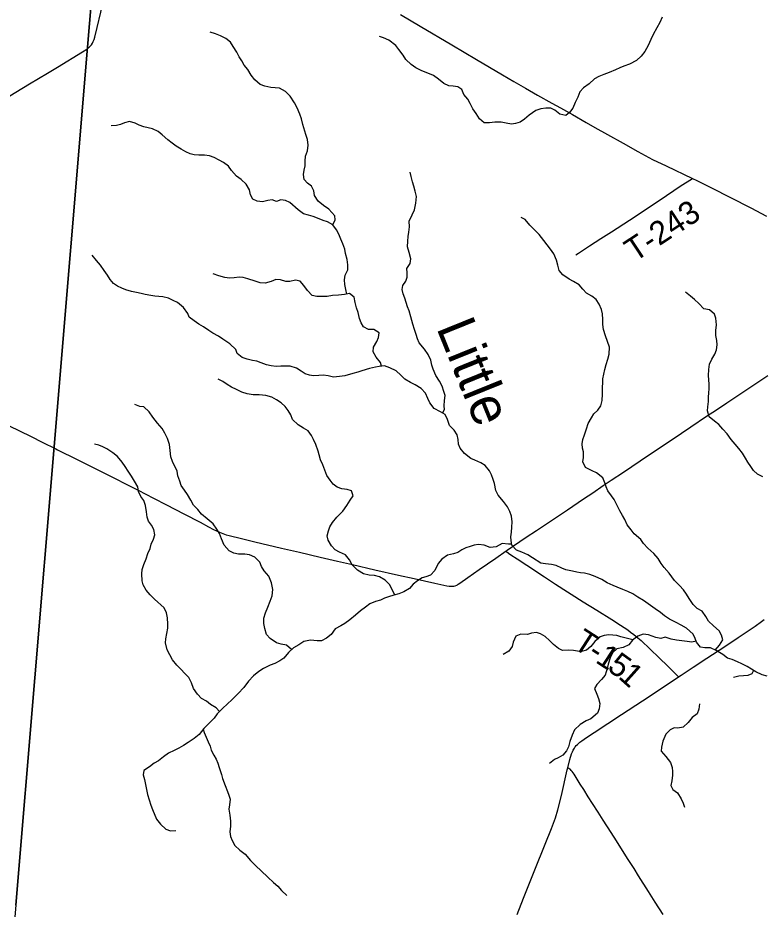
# Model space of a CAD drawing. Extents: x 0 to 1101, y 0 to 440.
# Drawn here: x 442.1 to 496.6, y 333.9 to 399.2 of the extents above; entities that cross this region are included whole.
import ezdxf

# ---------------------------------------------------------------- set-up
doc = ezdxf.new("R2010")
doc.units = 0
for name, color, linetype in [('GM_X_County_Road', 7, 'Continuous'), ('GM_X_Minor_River', 7, 'Continuous'), ('GM_X_Minor_River_Text', 7, 'Continuous'), ('GM_X_State_Route', 7, 'Continuous'), ('GM_X_Township_Road', 7, 'Continuous'), ('GM_X_Township_Road_Text', 7, 'Continuous')]:
    doc.layers.add(name, color=color, linetype=linetype)

msp = doc.modelspace()

# ---------------------------------------------------------------- linework, layer by layer
at = {"layer": 'GM_X_County_Road'}
for points in [[(441.919, 334.219), (444.709, 367.542), (447.185, 397.096), (448.107, 408.104), (416.196, 410.741)], [(447.303, 397.095), (447.325, 397.113), (447.405, 397.19), (447.471, 397.272), (447.537, 397.388), (447.597, 397.508), (447.659, 397.659), (447.718, 397.839), (447.897, 398.547), (448.161, 399.672), (448.67, 401.868), (448.936, 403.031), (449.312, 404.624), (449.637, 405.944), (449.838, 406.778), (450.23, 408.461)], [(470.094, 399.487), (471.558, 398.634), (473.867, 397.266), (475.677, 396.188), (477.57, 395.069), (478.42, 394.569), (479.257, 394.081), (480.151, 393.58), (481.19, 393.003), (481.824, 392.652), (482.698, 392.153), (483.716, 391.57), (484.351, 391.215), (485.281, 390.702), (486.412, 390.054), (487.483, 389.447), (488.569, 388.868), (489.561, 388.391), (491.499, 387.483), (491.811, 387.337), (492.842, 386.815), (495.762, 385.317), (496.923, 384.723)], [(420.004, 380.3), (420.984, 380.916), (423.156, 382.233), (423.231, 382.279), (425.059, 383.399), (428.052, 385.22), (429.936, 386.391), (432.42, 387.903), (433.884, 388.795), (436.362, 390.315), (437.628, 391.104), (438.966, 391.952), (440.938, 393.191), (441.919, 393.801), (442.941, 394.415), (444.239, 395.183), (444.988, 395.638), (446.8, 396.745), (447.132, 396.959), (447.235, 397.039), (447.303, 397.095)]]:
    msp.add_lwpolyline(points, dxfattribs=at)
msp.add_lwpolyline([(539, 244.322), (539, 402.783), (536.69, 402.914), (536.426, 402.929), (536.173, 402.942), (535.046, 402.998), (535.011, 403), (510.324, 404.394), (509.979, 404.414), (498.864, 405.041), (457.454, 407.541), (450.104, 407.972), (448.107, 408.104), (447.185, 397.096), (444.709, 367.542), (441.919, 334.219), (439.492, 305.784), (437.233, 279.3), (437.137, 278.176), (435.213, 255.629), (445.064, 254.562), (483.107, 250.705), (508.328, 247.799), (515.616, 246.993)], close=True, dxfattribs=at)
at = {"layer": 'GM_X_Minor_River'}
for points in [[(489.285, 399.3), (489.097, 398.915), (488.874, 398.52), (488.616, 398.034), (488.451, 397.661), (488.239, 397.231), (488.004, 396.768), (487.737, 396.43), (487.39, 396.117), (486.873, 395.863), (486.472, 395.698), (486.173, 395.578), (485.852, 395.446), (485.382, 395.237), (484.992, 395.095), (484.625, 394.941), (484.326, 394.786), (483.932, 394.405), (483.518, 394.127), (483.24, 393.824), (483.086, 393.439), (482.909, 393.054), (482.72, 392.636), (482.498, 392.309), (482.21, 392.086), (481.778, 392.195), (481.406, 392.474), (481.112, 392.615), (480.747, 392.632), (480.393, 392.581), (480.027, 392.461), (479.531, 392.105), (479.196, 391.814), (478.873, 391.602), (478.518, 391.494), (478.233, 391.464), (477.835, 391.527), (477.482, 391.59), (477.015, 391.608), (476.627, 391.546), (476.239, 391.564), (475.89, 391.842), (475.657, 392.233), (475.399, 392.567), (475.212, 392.98), (475.034, 393.279), (474.754, 393.637), (474.6, 394.004), (474.307, 394.19), (473.954, 394.241), (473.646, 394.258), (473.284, 394.423), (472.901, 394.748), (472.518, 395.016), (472.098, 395.182), (471.679, 395.37), (471.238, 395.594), (470.899, 395.815), (470.495, 396.197), (470.306, 396.519), (469.993, 396.934), (469.758, 397.223), (469.251, 397.618), (468.854, 397.772), (468.559, 397.879)], [(465.157, 384.084), (465.31, 384.434), (465.292, 384.742), (464.866, 385.215), (464.472, 385.484), (464.077, 385.809), (463.799, 386.223), (463.759, 386.577), (463.593, 386.909), (463.288, 387.119), (463.042, 387.408), (462.99, 387.761), (463.04, 388.08), (463.114, 388.409), (463.119, 388.739), (463.147, 389.103), (463.29, 389.499), (463.353, 389.908), (463.291, 390.319), (463.171, 390.697), (462.955, 391.44), (462.847, 391.852), (462.738, 392.184), (462.528, 392.643), (462.34, 393.01), (462.029, 393.516), (461.68, 393.852), (461.239, 394.098), (460.932, 394.126), (460.613, 394.142), (460.158, 394.24), (459.818, 394.371), (459.435, 394.696), (459.167, 395.053), (458.923, 395.467), (458.665, 395.767), (458.487, 396.089), (458.286, 396.377), (458.121, 396.721), (457.853, 397.146), (457.641, 397.457), (457.315, 397.736), (456.93, 397.935), (456.556, 398.067), (456.159, 398.187)], [(466.172, 379.006), (466.11, 379.343), (466.025, 379.709), (465.995, 380.04), (466.046, 380.392), (466.246, 380.787), (466.252, 381.14), (466.189, 381.528), (466.082, 381.974), (466.019, 382.282), (465.877, 382.683), (465.745, 383.038), (465.591, 383.394), (465.425, 383.704), (465.157, 384.084), (464.761, 384.295), (464.432, 384.402), (464.036, 384.568), (463.718, 384.687), (463.355, 384.784), (462.992, 384.892), (462.608, 385.171), (462.001, 385.704), (461.684, 385.869), (461.342, 385.897), (461.033, 385.799), (460.715, 385.907), (460.396, 385.866), (459.995, 385.77), (459.597, 385.81), (459.279, 385.952), (459.125, 386.273), (459.051, 386.65), (458.795, 387.064), (458.435, 387.4), (458.085, 387.633), (457.715, 388.049), (457.504, 388.382), (457.132, 388.65), (456.815, 388.826), (456.453, 389.002), (456.124, 389.122), (455.749, 389.184), (455.338, 389.191), (454.997, 389.219), (454.69, 389.292), (454.373, 389.422), (454.045, 389.621), (453.672, 389.843), (453.379, 390.064), (453.064, 390.308), (452.659, 390.668), (452.355, 390.911), (451.947, 391.111), (451.618, 391.196), (451.311, 391.269), (450.971, 391.389), (450.676, 391.53), (450.256, 391.639), (449.89, 391.554), (449.592, 391.433), (449.306, 391.358), (448.918, 391.341)], [(473.192, 370.279), (473.328, 370.532), (473.309, 370.817), (473.338, 371.192), (473.389, 371.567), (473.28, 371.865), (473.149, 372.254), (472.961, 372.632), (472.694, 373.024), (472.496, 373.494), (472.398, 373.791), (472.324, 374.157), (472.136, 374.581), (471.869, 374.961), (471.465, 375.434), (471.344, 375.72), (471.247, 376.041), (471.139, 376.418), (471.019, 376.807), (470.868, 377.333), (470.738, 377.779), (470.617, 378.077), (470.519, 378.386), (470.433, 378.695), (470.301, 379.027), (470.237, 379.336), (470.288, 379.642), (470.486, 379.947), (470.593, 380.241), (470.587, 380.549), (470.569, 380.868), (470.803, 381.24), (470.865, 381.58), (470.735, 382.049), (470.616, 382.461), (470.634, 382.882), (470.662, 383.223), (470.724, 383.53), (470.775, 383.928), (470.748, 384.349), (470.971, 384.801), (471.125, 385.186), (471.235, 385.663), (471.266, 386.152), (471.18, 386.552), (471.072, 386.907), (470.986, 387.238), (470.877, 387.616), (470.826, 387.947)], [(493.149, 352.906), (493.467, 353.266), (493.713, 353.661), (493.616, 354.004), (493.45, 354.325), (493.045, 354.684), (492.674, 355.02), (492.474, 355.365), (492.195, 355.756), (491.833, 355.955), (491.553, 356.256), (491.263, 356.681), (491.063, 357.015), (490.829, 357.337), (490.537, 357.649), (490.189, 358.007), (489.776, 358.549), (489.418, 358.976), (489.194, 359.264), (488.972, 359.62), (488.67, 360.001), (488.22, 360.372), (487.917, 360.718), (487.716, 361.006), (487.233, 361.435), (486.998, 361.734), (486.719, 362.092), (486.542, 362.481), (486.365, 362.78), (486.176, 363.125), (485.988, 363.515), (485.755, 363.94), (485.566, 364.227), (485.298, 364.584), (485.177, 364.871), (485.068, 365.18), (484.925, 365.524), (484.452, 365.907), (484.135, 366.037), (483.66, 366.295), (483.461, 366.708), (483.512, 367.037), (483.507, 367.436), (483.443, 367.721), (483.402, 368.018), (483.464, 368.336), (483.595, 368.698), (483.738, 369.117), (483.847, 369.525), (484.093, 369.931), (484.268, 370.225), (484.569, 370.504), (484.779, 370.82), (484.888, 371.205), (484.895, 371.661), (484.891, 372.173), (484.919, 372.503), (484.935, 372.787), (485.009, 373.139), (485.083, 373.468), (485.168, 373.843), (485.299, 374.228), (485.396, 374.602), (485.416, 375.103), (485.274, 375.537), (485.121, 375.95), (484.98, 376.396), (484.928, 376.773), (484.934, 377.148), (484.895, 377.559), (484.831, 377.867), (484.666, 378.268), (484.444, 378.602), (484.128, 378.846), (483.721, 379.057), (483.463, 379.369), (483.206, 379.669), (482.788, 379.914), (482.46, 380.09), (482.009, 380.416), (481.74, 380.728), (481.621, 381.128), (481.535, 381.482), (481.337, 381.952), (481.103, 382.298), (480.857, 382.609), (480.611, 382.932), (480.253, 383.37), (479.883, 383.763), (479.591, 384.052), (479.243, 384.456), (478.938, 384.609)], [(457.08, 375.693), (456.765, 375.926), (456.369, 376.148), (456.076, 376.324), (455.669, 376.603), (455.342, 376.802), (454.992, 377.047), (454.631, 377.303), (454.533, 377.589), (454.221, 378.026), (453.781, 378.375), (453.453, 378.539), (453.114, 378.693), (452.693, 378.802), (452.113, 378.856), (451.817, 378.907), (451.408, 378.981), (451.101, 379.054), (450.76, 379.117), (450.407, 379.191), (449.976, 379.323), (449.682, 379.441), (449.365, 379.583), (449.071, 379.769), (448.848, 380.069), (448.647, 380.379), (448.39, 380.725), (448.134, 381.116), (447.843, 381.474), (447.53, 381.854)], [(468.724, 373.714), (468.65, 373.986), (468.314, 374.367), (468.115, 374.78), (468.12, 375.11), (468.377, 375.516), (468.484, 375.811), (468.535, 376.174), (468.151, 376.408), (467.764, 376.403), (467.39, 376.591), (467.224, 376.889), (467.103, 377.21), (466.996, 377.644), (466.876, 377.999), (466.791, 378.388), (466.705, 378.765), (466.379, 379.054), (466.013, 378.969), (465.568, 378.919), (465.134, 378.892), (464.734, 378.818), (464.357, 378.813), (463.97, 378.83), (463.641, 378.904), (463.293, 379.262), (463.025, 379.619), (462.756, 379.942), (462.404, 380.016), (462.003, 379.931), (461.695, 379.925), (461.321, 380.044), (460.979, 380.061), (460.624, 379.93), (460.188, 379.812), (459.824, 379.817), (459.472, 379.937), (458.916, 380.128), (458.576, 380.213), (458.28, 380.24), (457.925, 380.189), (457.571, 380.16), (457.23, 380.222), (456.799, 380.343), (456.39, 380.475)], [(496.647, 365.615), (496.262, 365.814), (495.959, 366.069), (495.769, 366.368), (495.558, 366.679), (495.369, 366.989), (495.169, 367.334), (494.9, 367.68), (494.621, 368.014), (494.318, 368.349), (494.039, 368.752), (493.725, 369.098), (493.434, 369.433), (493.096, 369.689), (492.713, 370.002), (492.595, 370.448), (492.622, 370.744), (492.662, 371.141), (492.679, 371.449), (492.695, 371.767), (492.711, 372.063), (492.705, 372.405), (492.687, 372.724), (492.669, 373.043), (492.687, 373.487), (492.739, 373.862), (492.915, 374.223), (493.138, 374.607), (493.257, 374.924), (493.296, 375.276), (493.267, 375.595), (493.205, 375.972), (493.199, 376.337), (493.251, 376.746), (493.201, 377.225), (493.114, 377.522), (492.732, 377.858), (492.334, 377.921), (491.964, 378.303), (491.649, 378.604), (491.345, 378.848), (490.973, 379.15)], [(488.755, 355.935), (488.416, 356.179), (487.909, 356.54), (487.503, 356.797), (487.119, 357.042), (486.756, 357.207), (486.394, 357.361), (485.975, 357.527), (485.68, 357.645), (485.25, 357.834), (484.843, 358.079), (484.356, 358.303), (483.971, 358.457), (483.585, 358.543), (483.3, 358.582), (483.016, 358.632), (482.698, 358.693), (482.209, 358.792), (481.915, 358.922), (481.507, 359.099), (481.178, 359.173), (480.722, 359.225), (480.381, 359.287), (479.771, 359.661), (479.444, 359.894), (478.991, 360.083), (478.606, 360.226), (478.27, 360.607), (478.206, 360.938), (478.2, 361.223), (478.239, 361.564), (478.267, 361.916), (478.296, 362.314), (478.246, 362.725), (478.114, 363.068), (477.949, 363.412), (477.658, 363.804), (477.255, 364.266), (477.101, 364.61), (476.983, 365.124), (476.885, 365.41), (476.765, 365.765), (476.633, 366.051), (476.308, 366.432), (475.992, 366.631), (475.551, 366.831), (475.256, 366.95), (474.794, 367.321), (474.47, 367.713), (474.349, 368.011), (474.32, 368.342), (474.268, 368.696), (474.034, 369.029), (473.697, 369.376), (473.556, 369.8), (473.39, 370.167), (473.04, 370.366), (472.577, 370.623), (472.252, 371.027), (472.109, 371.359), (471.944, 371.749), (471.619, 372.084), (471.178, 372.353), (470.839, 372.518), (470.432, 372.763), (470.129, 373.064), (469.781, 373.388), (469.328, 373.589), (468.942, 373.743), (468.554, 373.692), (468.268, 373.639), (467.845, 373.544), (467.284, 373.382), (466.974, 373.284), (466.619, 373.176), (466.035, 373.014), (465.635, 372.952), (465.201, 372.925), (464.803, 372.999), (464.451, 373.062), (464.131, 373.032), (463.732, 373.004), (463.436, 373.066), (463.13, 373.162), (462.836, 373.349), (462.498, 373.57), (462.021, 373.714), (461.645, 373.709), (461.337, 373.714), (461.006, 373.707), (460.63, 373.736), (460.29, 373.821), (459.904, 373.952), (459.575, 374.083), (459.268, 374.145), (458.882, 374.23), (458.519, 374.35), (458.136, 374.64), (458.038, 374.938), (457.611, 375.366), (457.08, 375.693)], [(469.691, 356.951), (469.308, 357.719), (468.994, 358.043), (468.565, 358.277), (468.19, 358.374), (467.814, 358.414), (467.394, 358.512), (466.965, 358.757), (466.572, 359.151), (466.372, 359.518), (466.07, 359.899), (465.64, 360.099), (465.323, 360.252), (465.043, 360.563), (464.798, 360.966), (464.746, 361.274), (464.832, 361.648), (464.939, 361.943), (465.127, 362.27), (465.452, 362.652), (465.881, 363.089), (466.172, 363.506), (466.429, 363.911), (466.639, 364.216), (466.508, 364.593), (466.202, 364.678), (465.815, 364.729), (465.464, 364.86), (465.17, 365.07), (464.947, 365.358), (464.713, 365.703), (464.571, 366.104), (464.417, 366.482), (464.24, 366.86), (464.155, 367.214), (464.068, 367.5), (463.904, 367.97), (463.739, 368.337), (463.584, 368.635), (463.35, 368.98), (463.011, 369.179), (462.604, 369.413), (462.2, 369.807), (462.08, 370.15), (461.868, 370.472), (461.667, 370.76), (461.364, 371.026), (461.025, 371.259), (460.674, 371.436), (460.232, 371.568), (459.742, 371.61), (459.309, 371.616), (458.865, 371.68), (458.491, 371.811), (458.084, 372), (457.722, 372.188), (457.406, 372.386), (457.101, 372.585), (456.761, 372.761)], [(462.13, 352.959), (461.759, 353.261), (461.373, 353.347), (461.032, 353.443), (460.547, 353.758), (460.289, 354.047), (460.171, 354.504), (460.085, 354.87), (460.103, 355.256), (460.212, 355.653), (460.378, 356.06), (460.567, 356.49), (460.71, 356.898), (460.751, 357.364), (460.668, 357.843), (460.459, 358.324), (460.111, 358.717), (459.934, 359.038), (459.79, 359.348), (459.443, 359.718), (459.047, 359.895), (458.705, 359.934), (458.227, 359.953), (457.897, 360.027), (457.557, 360.18), (457.199, 360.607), (456.99, 361.077), (456.836, 361.444), (456.647, 361.765), (456.38, 362.168), (455.952, 362.539), (455.536, 362.875), (455.256, 363.21), (454.942, 363.522), (454.742, 363.89), (454.509, 364.315), (454.286, 364.625), (454.029, 364.971), (453.932, 365.291), (453.801, 365.68), (453.738, 366.034), (453.407, 366.723), (453.275, 367.078), (453.225, 367.545), (453.175, 367.99), (453.045, 368.424), (452.846, 368.815), (452.646, 369.148), (452.31, 369.552), (451.952, 369.979), (451.685, 370.37), (451.303, 370.729), (451.018, 370.767), (450.655, 370.898)], [(456.859, 348.411), (456.602, 348.686), (456.184, 348.921), (455.891, 349.164), (455.518, 349.364), (455.238, 349.675), (454.948, 350.09), (454.784, 350.513), (454.607, 350.892), (453.721, 351.805), (453.396, 352.209), (453.197, 352.565), (453.02, 352.92), (452.891, 353.446), (452.907, 353.742), (453.056, 354.513), (453.072, 354.82), (453.045, 355.276), (452.971, 355.642), (452.783, 355.997), (452.086, 356.646), (451.772, 356.958), (451.481, 357.293), (451.259, 357.683), (451.172, 357.992), (451.146, 358.505), (451.185, 358.811), (451.294, 359.185), (451.471, 359.592), (451.591, 360), (451.757, 360.362), (451.853, 360.668), (452.018, 361.052), (452.103, 361.347), (452.029, 361.758), (451.863, 362.057), (451.651, 362.367), (451.542, 362.654), (451.491, 363.041), (451.429, 363.509), (451.298, 363.864), (451.075, 364.175), (450.921, 364.53), (450.858, 364.873), (450.625, 365.298), (450.391, 365.654), (450.146, 366.034), (449.935, 366.356), (449.712, 366.689), (449.376, 367.093), (449.038, 367.372), (448.587, 367.652), (448.293, 367.816), (447.998, 367.934), (447.691, 367.996)], [(478.255, 360.683), (478.02, 360.679), (477.553, 360.732), (477.105, 360.488), (476.682, 360.438), (476.229, 360.605), (475.83, 360.645), (475.499, 360.593), (475.201, 360.507), (474.892, 360.398), (474.604, 360.266), (474.294, 360.066), (473.984, 359.957), (473.561, 359.861), (473.123, 359.583), (472.867, 359.257), (472.62, 358.749), (472.295, 358.401), (471.974, 358.281), (471.688, 358.205), (471.354, 357.994), (471.042, 357.749), (470.763, 357.434), (470.361, 357.19), (469.982, 357.037), (469.615, 356.929), (469.226, 356.81), (468.939, 356.712), (468.629, 356.58), (468.286, 356.471), (467.861, 356.307), (467.549, 356.062), (467.169, 355.783), (466.81, 355.459), (466.406, 355.123), (466.026, 354.856), (465.726, 354.69), (465.313, 354.469), (465.033, 354.064), (464.675, 353.796), (464.318, 353.585), (464.01, 353.579), (463.521, 353.632), (463.029, 353.549), (462.66, 353.304), (462.258, 353.083), (461.911, 352.747), (461.562, 352.331), (461.274, 352.13), (460.906, 351.931), (460.55, 351.8), (460.079, 351.569), (459.722, 351.335), (459.33, 351.034), (458.97, 350.641), (458.632, 350.18), (458.215, 349.731), (457.775, 349.294), (457.416, 348.947), (457.08, 348.645), (456.686, 348.23), (456.465, 347.926), (456.094, 347.556), (455.7, 347.164), (455.352, 346.737), (454.993, 346.424), (454.544, 346.135), (454.221, 345.912), (453.865, 345.724), (453.52, 345.559), (453.118, 345.349), (452.749, 345.082), (452.368, 344.792), (452.069, 344.625), (451.711, 344.347), (451.296, 344.08), (451.246, 343.773), (451.343, 343.419), (451.417, 343.065), (451.491, 342.688), (451.577, 342.322), (451.696, 341.945), (451.827, 341.556), (451.947, 341.235), (452.244, 340.514), (452.534, 340.145), (452.905, 339.786), (453.268, 339.667), (453.645, 339.683)], [(496.955, 350.992), (496.592, 351.1), (496.128, 351.312), (495.812, 351.522), (495.495, 351.72), (495.099, 351.909), (494.782, 352.062), (494.409, 352.215), (494.068, 352.323), (493.719, 352.579), (493.222, 352.871), (492.803, 353.071), (492.404, 353.089), (492.074, 353.128), (491.795, 353.485), (491.685, 353.772), (491.553, 354.081), (491.059, 354.522), (490.663, 354.744), (490.29, 354.943), (489.815, 355.179), (489.454, 355.423), (489.149, 355.667), (488.755, 355.935)], [(487.126, 353.661), (486.237, 353.891), (485.942, 353.975), (485.658, 354.014), (485.373, 354.03), (485.03, 353.99), (484.721, 353.892), (484.35, 353.545), (484.048, 353.174), (483.725, 352.894), (483.358, 352.798), (483.074, 352.836), (482.778, 352.875), (482.414, 352.915), (481.98, 352.887), (481.674, 353.029), (481.314, 353.33), (481.022, 353.62), (480.696, 353.898), (480.357, 354.108), (480.062, 354.204), (479.697, 354.141), (479.399, 354.066), (478.932, 354.085), (478.553, 353.92), (478.364, 353.502), (478.29, 353.173), (478.034, 352.835), (477.631, 352.591)], [(491.767, 353.559), (491.453, 353.502), (491.1, 353.542), (490.713, 353.582), (490.326, 353.634), (489.94, 353.719), (489.497, 353.852), (489.165, 353.754), (488.813, 353.839), (488.269, 354.019), (487.87, 354.07), (487.492, 353.94), (487.111, 353.65), (486.844, 353.301), (486.419, 353.091), (485.95, 353.008), (485.637, 352.716), (485.461, 352.355), (485.328, 351.89), (485.254, 351.561), (485.098, 351.063), (484.82, 350.748), (484.484, 350.401), (484.319, 350.085), (484.495, 349.683), (484.604, 349.352), (484.701, 348.986), (484.661, 348.599), (484.531, 348.294), (484.056, 347.869), (483.701, 347.738), (483.263, 347.449), (482.858, 347.079), (482.681, 346.672), (482.514, 346.208), (482.417, 345.823), (482.275, 345.529), (481.997, 345.203), (481.663, 345.015), (481.376, 344.883), (481.029, 344.592)], [(495.976, 351.413), (495.84, 351.18), (495.542, 351.059), (495.234, 351.019), (494.891, 350.99), (494.502, 350.893)], [(492.009, 348.974), (491.969, 348.576), (491.838, 348.248), (491.469, 347.981), (491.178, 347.598), (490.808, 347.251), (490.431, 347.2), (490.146, 347.216), (489.859, 347.072), (489.535, 346.759), (489.321, 346.238), (489.223, 345.807), (489.196, 345.512), (489.532, 345.108), (489.878, 344.682), (489.998, 344.315), (490.039, 344.019), (490.035, 343.734), (489.971, 343.325), (489.909, 342.985), (490.052, 342.687), (490.391, 342.442), (490.658, 342.017), (490.824, 341.696), (490.91, 341.398)], [(455.661, 347.116), (455.73, 346.867), (455.873, 346.524), (456.027, 346.191), (456.17, 345.859), (456.245, 345.573), (456.422, 345.217), (456.6, 344.907), (456.721, 344.621), (456.83, 344.3), (456.993, 343.797), (457.068, 343.511), (457.265, 342.996), (457.441, 342.56), (457.539, 342.274), (457.637, 341.988), (457.574, 341.568), (457.523, 341.262), (457.596, 340.805), (457.657, 340.372), (457.641, 340.019), (457.611, 339.598), (457.651, 339.256), (457.784, 338.958), (457.972, 338.602), (458.343, 338.255), (458.737, 337.964), (459.117, 337.492), (459.499, 337.099), (459.904, 336.728), (460.398, 336.276), (460.814, 335.883), (461.117, 335.605), (461.397, 335.293), (461.779, 334.923)]]:
    msp.add_lwpolyline(points, dxfattribs=at)
at = {"layer": 'GM_X_State_Route'}
for points in [[(478.66, 333.534), (479.123, 334.733), (479.953, 336.81), (480.696, 338.681), (481.157, 339.841), (481.457, 340.625), (481.632, 341.197), (481.89, 342.248), (482.322, 344.137), (482.357, 344.281), (482.514, 344.896), (482.637, 345.306), (482.697, 345.457), (482.749, 345.572), (482.798, 345.662), (482.844, 345.736), (482.907, 345.826), (482.984, 345.919), (483.063, 346.002), (483.137, 346.07), (483.249, 346.163), (483.384, 346.262), (483.731, 346.5), (484.3, 346.87), (486.299, 348.2), (487.828, 349.199), (489.568, 350.353), (490.467, 350.945), (490.657, 351.071), (491.555, 351.67), (492.547, 352.329), (493.857, 353.186), (494.852, 353.844), (496.094, 354.668), (496.561, 355.011), (496.737, 355.145)], [(489.343, 333.542), (488.769, 334.436), (488.282, 335.209), (487.546, 336.375), (487.217, 336.894), (486.787, 337.569), (486.496, 338.024), (485.927, 338.921), (485.526, 339.544), (484.948, 340.441), (484.579, 341.023), (484.168, 341.667), (483.857, 342.154), (483.525, 342.691), (483.279, 343.086), (482.819, 343.809), (482.691, 344.005), (482.616, 344.095), (482.555, 344.154), (482.502, 344.196), (482.439, 344.235), (482.357, 344.281)]]:
    msp.add_lwpolyline(points, dxfattribs=at)
at = {"layer": 'GM_X_Township_Road'}
for points in [[(482.944, 381.871), (483.146, 382.005), (483.958, 382.533), (484.783, 383.071), (485.566, 383.574), (486.88, 384.425), (489.138, 385.909), (490.604, 386.9), (491.499, 387.483)], [(420.004, 380.3), (421.81, 379.387), (422.71, 378.939), (423.939, 378.316), (424.699, 377.918), (425.725, 377.387), (426.739, 376.875), (427.638, 376.423), (429.098, 375.679), (430.9, 374.741), (432.089, 374.126), (433.165, 373.57), (434.152, 373.043), (436.647, 371.741), (437.294, 371.412), (438.382, 370.882), (438.441, 370.853), (439.035, 370.563), (440.217, 369.971), (441.379, 369.379), (443.049, 368.562), (443.846, 368.156), (444.847, 367.656)], [(477.838, 360.174), (477.919, 360.23), (479.318, 361.188), (480.064, 361.682), (482.33, 363.187), (483.52, 363.988), (484.198, 364.447), (484.948, 364.963), (485.535, 365.359), (486.432, 365.962), (487.669, 366.792), (489.004, 367.68), (490.008, 368.357), (491.369, 369.272), (492.532, 370.047), (493.245, 370.522), (494.022, 371.035), (497.015, 373.03)], [(444.847, 367.656), (444.861, 367.649), (444.969, 367.597)], [(444.969, 367.597), (445.132, 367.52), (446.279, 366.959), (447.192, 366.497), (447.794, 366.202), (448.807, 365.692), (450.343, 364.902), (450.89, 364.621), (452.011, 364.034), (452.959, 363.554), (454.236, 362.904), (455.424, 362.284), (456.041, 361.952), (456.416, 361.745), (456.633, 361.64), (456.853, 361.543), (457.091, 361.454), (457.346, 361.368), (457.559, 361.309), (458.46, 361.078), (459.439, 360.847), (461.381, 360.389), (462.698, 360.079), (464.222, 359.723), (465.493, 359.431), (466.58, 359.175), (468.215, 358.804), (469.961, 358.414), (471.106, 358.154), (472.617, 357.821), (473.502, 357.626), (473.669, 357.601), (473.817, 357.588), (473.917, 357.588), (474.016, 357.603), (474.118, 357.628), (474.222, 357.672), (474.274, 357.703), (474.337, 357.742), (474.447, 357.816), (475.047, 358.223), (475.867, 358.807), (477.094, 359.653), (477.838, 360.174)], [(477.838, 360.174), (477.874, 360.144), (478.029, 360.016), (478.195, 359.902), (478.643, 359.61), (479.357, 359.138), (480.646, 358.285), (481.468, 357.739), (483.497, 356.449), (484.478, 355.838), (485.59, 355.158), (486.226, 354.749), (486.753, 354.392), (486.966, 354.236), (487.199, 354.057), (487.499, 353.812), (487.74, 353.603), (489.063, 352.346), (489.688, 351.734), (490.435, 350.977), (490.467, 350.945)]]:
    msp.add_lwpolyline(points, dxfattribs=at)

# ---------------------------------------------------------------- texts
at = {"layer": 'GM_X_Minor_River_Text'}
msp.add_text('Little', height=2.8413, rotation=292.02211, dxfattribs=at).set_placement((472.709, 376.54))
at = {"layer": 'GM_X_Township_Road_Text'}
for s, height, rotation, p in [('T-243', 1.7045, 33.38959, (487.255, 381.313)), ('T', 1.705, 327.15508, (482.651, 353.125)), ('-', 1.705, 327.10671, (483.722, 352.434)), ('1', 1.705, 326.88582, (484.309, 352.055)), ('5', 1.705, 323.93781, (485.169, 351.494)), ('1', 1.705, 318.34313, (485.983, 350.904))]:
    msp.add_text(s, height=height, rotation=rotation, dxfattribs=at).set_placement(p)

doc.saveas('drawing.dxf')
